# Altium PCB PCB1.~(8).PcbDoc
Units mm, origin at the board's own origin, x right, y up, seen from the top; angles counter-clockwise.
Board outline 65.66 x 57.02 mm, 2 copper layers (Top Layer, Bottom Layer); 3 components, 3 nets, 18 pads, 0 vias.
Unrouted connection lines stored in the file: 3.
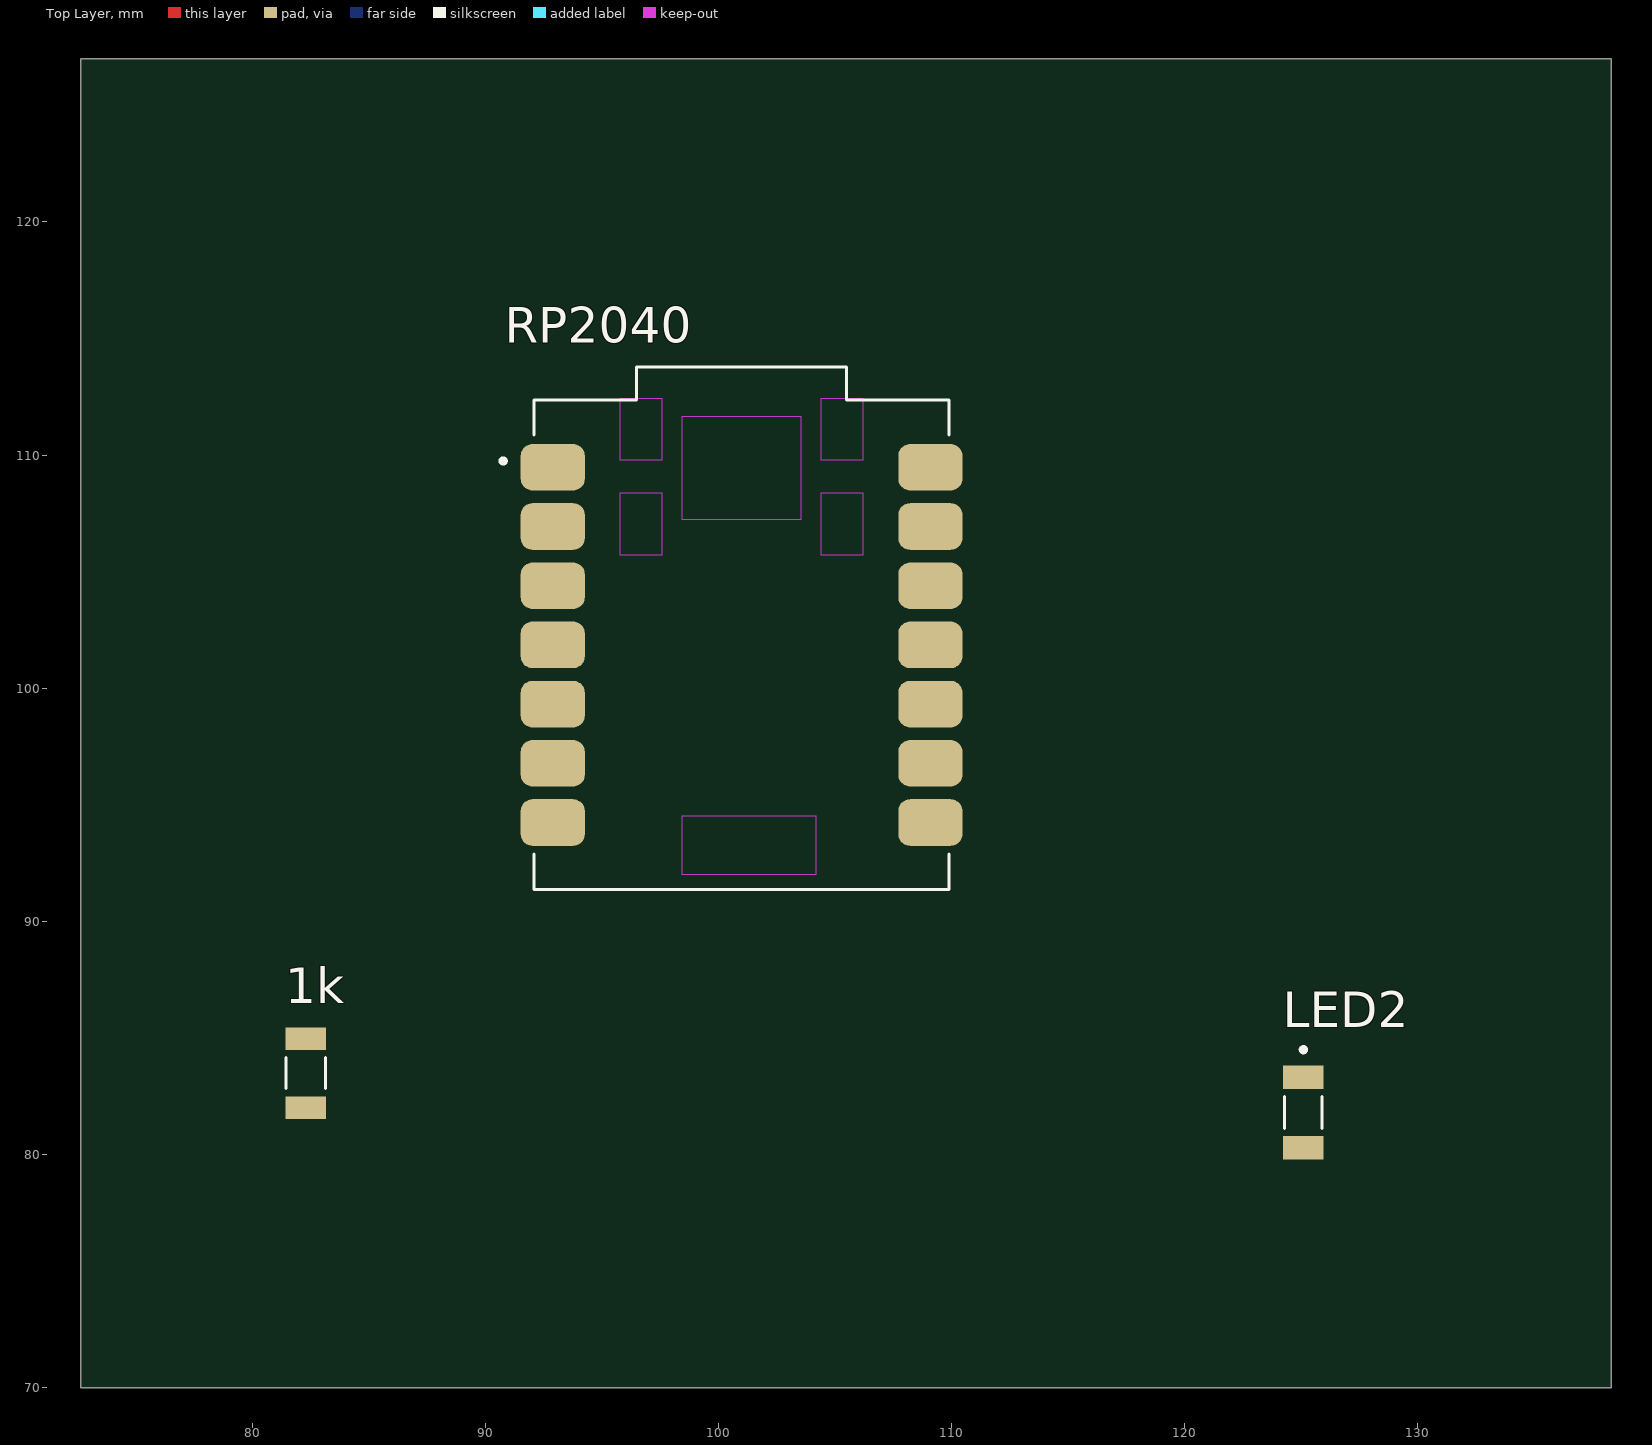
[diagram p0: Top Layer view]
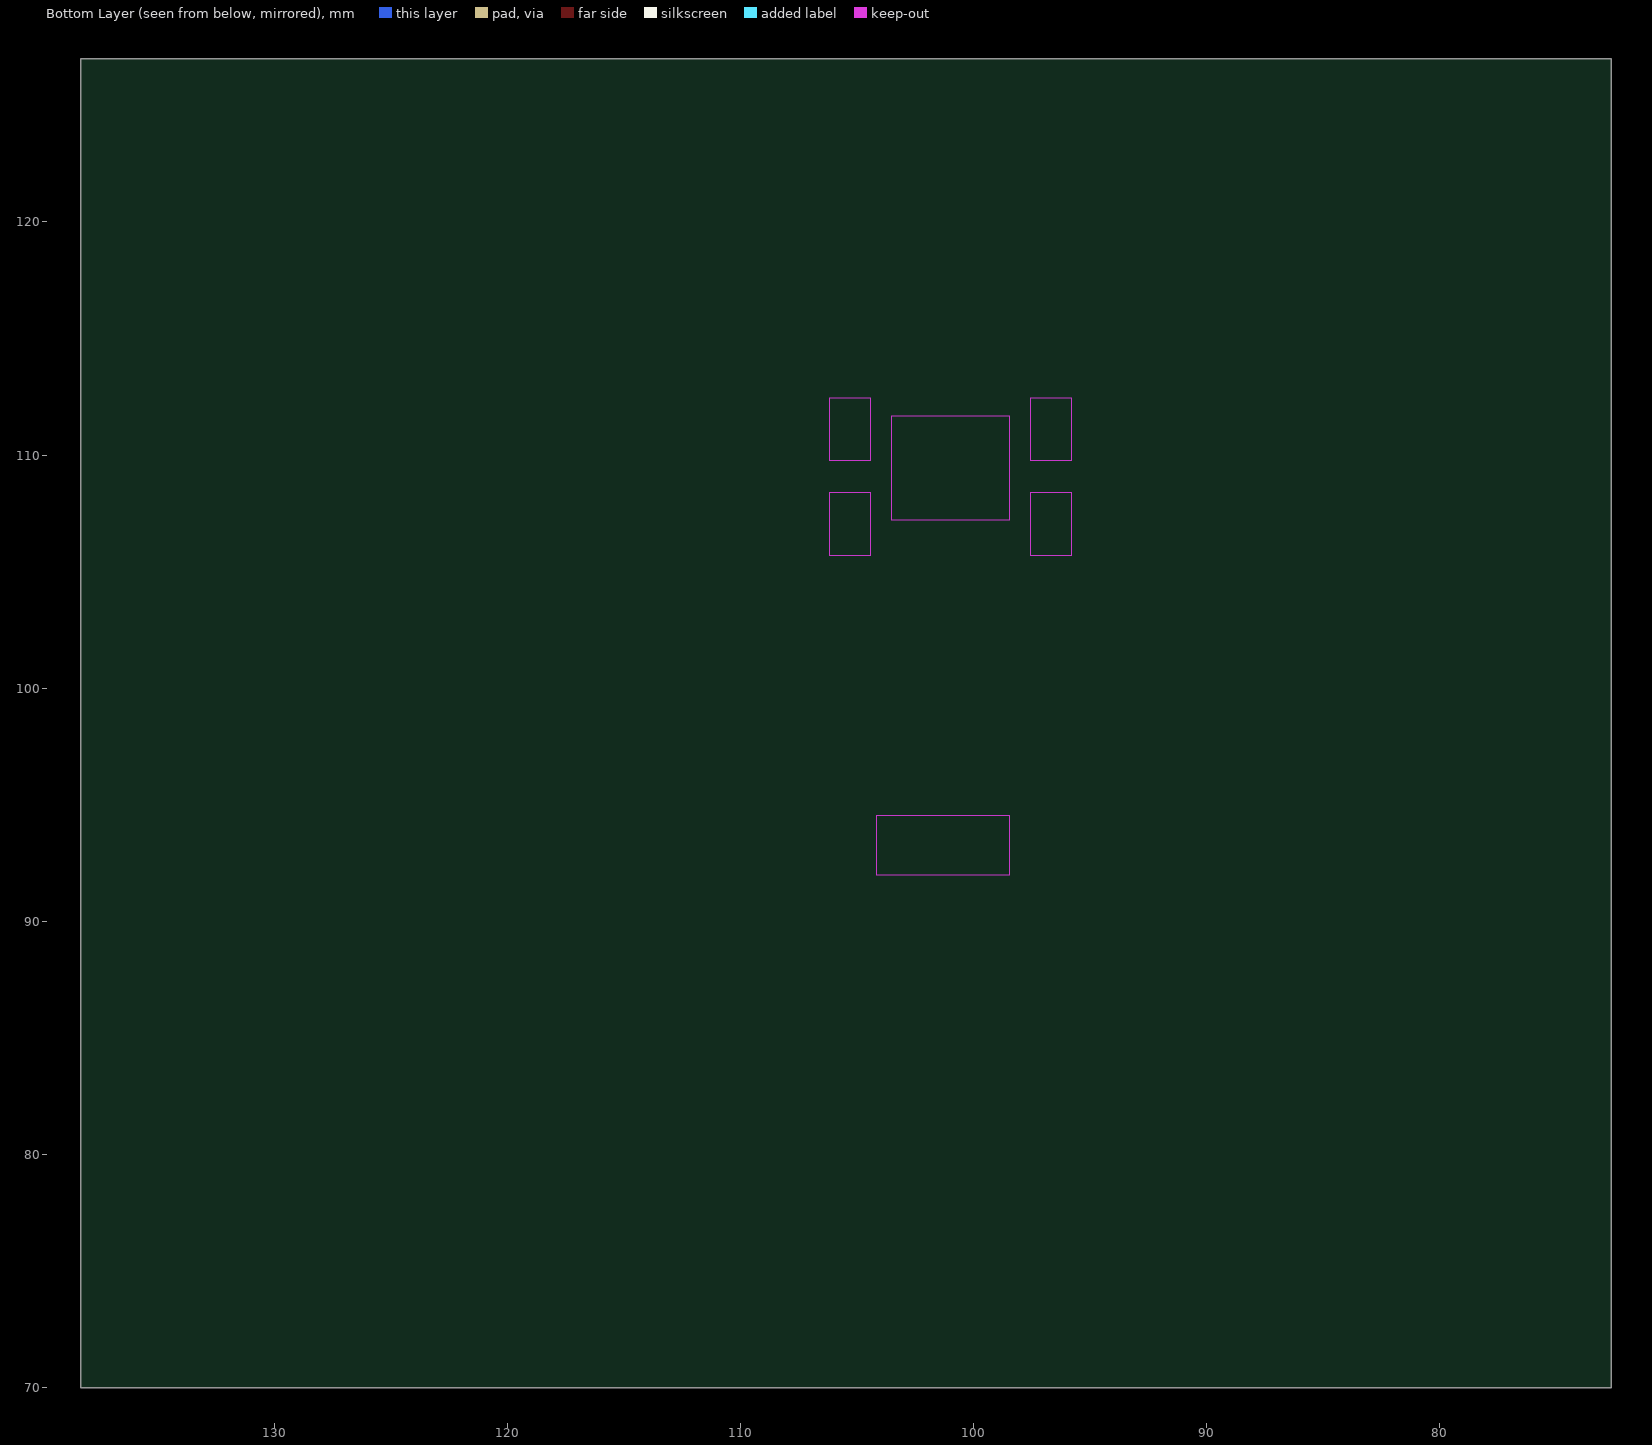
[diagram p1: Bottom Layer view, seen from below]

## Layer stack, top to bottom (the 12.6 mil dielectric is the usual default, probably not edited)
Top Solder: solder mask 0.0102, Solder Resist, Dk 3.5
Top Layer: signal copper 0.0356
Dielectric 1: dielectric 0.32, FR-4, Dk 4.8
Bottom Layer: signal copper 0.0356
Bottom Solder: solder mask 0.0102, Solder Resist, Dk 3.5

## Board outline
72.644,69.977 138.303,69.977 138.303,127 72.644,127

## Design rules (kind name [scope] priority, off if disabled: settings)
Clearance [All] p1: gap=0.254 ignorepadtopadclearanceinfootprint=FALSE except(0: Arc-Hole Track-Hole SMDPad-Hole THPad-Hole Via-Hole Fill-Hole Poly-Hole Region-Hole Text-Hole)
PolygonConnect [All] p1: connectstyle=Relief reliefconductorwidth=0.254 reliefentries=4 polygonreliefangle="90 Angle" airgapwidth=0.254
RoutingVias [All] p1: holewidth=0.711 width=1.27 viastyle="Through Hole" minholewidth=0.711 minwidth=1.27 maxholewidth=0.711 maxwidth=1.27
SolderMaskExpansion [All] p1: expansion=0.102 istentingtop=FALSE
Width [All] p1: maxlimit=0.254 minlimit=0.254 preferedwidth=0.254
30 further rules are at their usual default settings.

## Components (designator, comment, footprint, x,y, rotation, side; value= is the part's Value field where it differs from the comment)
1k "1k" 1k 82.296,83.483 r90 top
LED2 "LHN974_RED_LED_1206" LED2 125.095,81.788 r270 top
RP2040 "102010428" 102010428 100.993,101.854 r0 top

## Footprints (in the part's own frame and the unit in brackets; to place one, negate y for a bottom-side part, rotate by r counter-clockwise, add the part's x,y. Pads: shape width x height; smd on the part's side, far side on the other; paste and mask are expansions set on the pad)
1k [mm]
  rect 0.97x1.73 smd: 1(-1.48,0) 2(1.48,0)
  silkscreen extent -0.67,-0.85 0.67,0.85, body extent -1.55,-0.8 1.55,0.8, height 0.65
102010428 [mm]
  rrect50% 2.75x2 smd: 1(-8.1,7.62) 2(-8.1,5.08) 3(-8.1,2.54) 4(-8.1,0) 5(-8.1,-2.54) 6(-8.1,-5.08) 7(-8.1,-7.62) 8(8.1,-7.62) 9(8.1,-5.08) 10(8.1,-2.54) 11(8.1,0) 12(8.1,2.54) 13(8.1,5.08) 14(8.1,7.62)
  Keep-Out Layer region: 2.54,5.375 -2.54,5.375 -2.54,9.82 2.54,9.82
  Keep-Out Layer region: 5.207,7.915 3.429,7.915 3.429,10.582 5.207,10.582
  Keep-Out Layer region: 5.207,3.851 3.429,3.851 3.429,6.518 5.207,6.518
  Keep-Out Layer region: -3.429,3.851 -5.207,3.851 -5.207,6.518 -3.429,6.518
  Keep-Out Layer region: -3.429,7.915 -5.207,7.915 -5.207,10.582 -3.429,10.582
  Keep-Out Layer region: 3.175,-9.865 -2.54,-9.865 -2.54,-7.325 3.175,-7.325
  silkscreen extent -10.33,-10.5 8.9,11.92, body extent -8.75,-10.5 8.75,11.5, height 4.41
LED2 [mm] "LEDC3216X120N"
  rect 1.01x1.73 smd: NEG(1.51,0) POS(-1.51,0)
  silkscreen extent -2.8,-0.8 0.68,0.8, body extent -1.6,-0.8 1.6,0.8, height 1.2

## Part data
1k: "Res Thick Film 3.2 x 1.6 mm 6.8K Ohm 1% 0.25W(1/4W) 100ppm/ C Molded SMD Paper T/R", Package=None
LED2: library part LED2, "2.6 V Red LED SMD", Package=None
RP2040: "RP2040 XIAO RP2040 series ARMÂ® CortexÂ®-M0+ MCU 32-Bit Embedded Evaluation Board", Package=None

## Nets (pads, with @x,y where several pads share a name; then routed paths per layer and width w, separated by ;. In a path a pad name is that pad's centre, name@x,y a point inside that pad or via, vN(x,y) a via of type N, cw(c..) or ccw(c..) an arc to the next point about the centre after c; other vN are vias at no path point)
Net1k_1: 1k.1 LED2.NEG
Net1k_2: 1k.2 RP2040.1
NetLED2_POS: LED2.POS RP2040.13
pads on no net: RP2040.2 RP2040.3 RP2040.4 RP2040.5 RP2040.6 RP2040.7 RP2040.8 RP2040.9 RP2040.10 RP2040.11 RP2040.12 RP2040.14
